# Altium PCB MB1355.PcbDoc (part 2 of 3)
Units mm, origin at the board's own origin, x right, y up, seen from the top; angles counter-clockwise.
Board outline 70.13 x 64.58 mm, 4 copper layers (L1, L2, L3, L4), stack 1.565 mm thick; 213 components, 161 nets, 1280 pads, 261 vias.
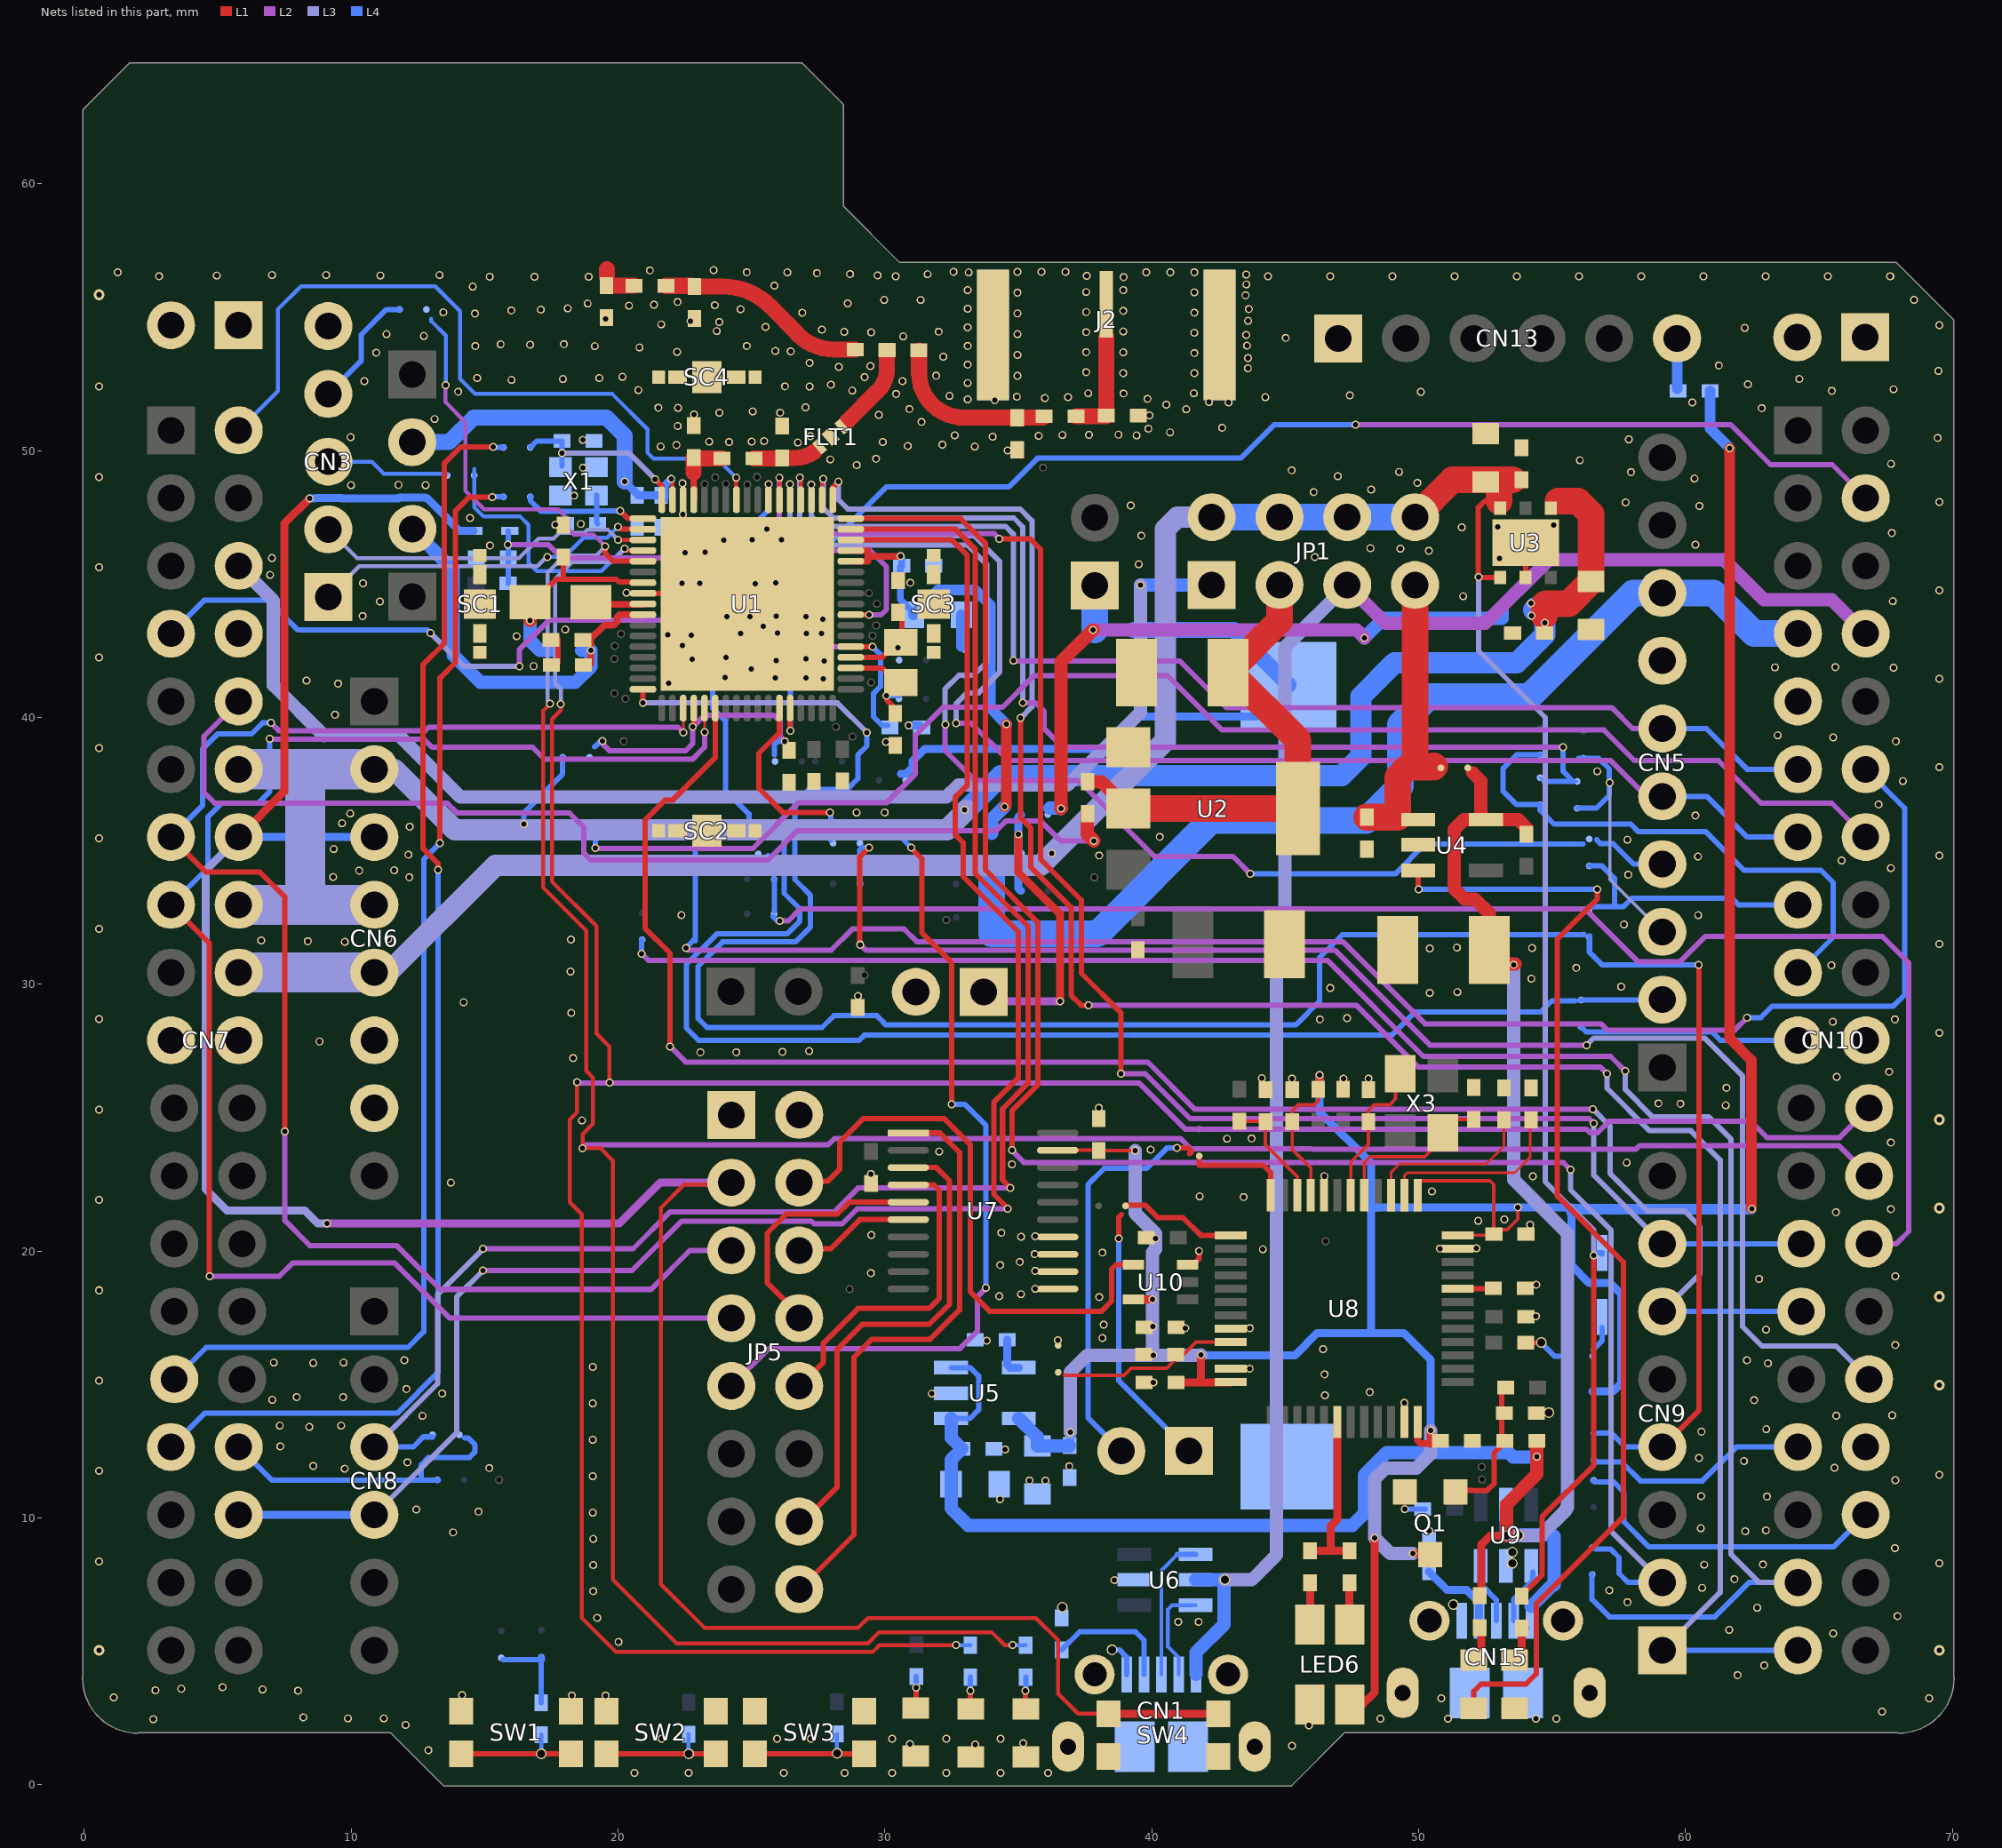
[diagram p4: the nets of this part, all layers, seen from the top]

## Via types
v1: diameter 0.3, hole 0.2, L1 to L4, tented both sides, 254 vias
v2: diameter 0.406, hole 0.203, L1 to L4, tented both sides, 7 vias

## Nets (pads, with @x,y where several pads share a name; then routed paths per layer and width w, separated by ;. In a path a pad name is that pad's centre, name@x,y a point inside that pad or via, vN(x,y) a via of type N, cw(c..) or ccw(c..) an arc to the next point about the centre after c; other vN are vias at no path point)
3V3: C13.1 C16.1 CN6.2 CN6.4 CN7.12 CN7.16 pad.105 pad.106 SB26.2 SB33.2 U3.4 | length 75.4
  L1 w1: 54.718,43.816 54.718,44.222 54.755,44.259 55.619,44.259 C13.1@56.46,45.1 56.46,47.616 55.967,48.109 55.224,48.109
  L3 w0.8: CN6.2@10.87,38.06 11.615,38.06 13.894,35.781 27.12,35.781 27.122,35.783 27.66,35.783 27.662,35.781 32.321,35.781 v1@33.055,36.515
  L3 w1.5: CN7.16@5.79,32.98 8.287,32.98 ; CN7.12@5.79,38.06 8.242,38.06 ; CN6.4@10.87,32.98 8.287,32.98 ; CN6.2@10.87,38.06 8.242,38.06 ; 8.242,38.06 8.287,38.015 8.287,32.98
  L4 w0.2: v1(16.475,36.002) 16.475,36.427 17.927,37.879 SB33.2@17.927,38.505
  L4 w0.8: v1@33.066,36.536 34.35,37.82 47.117,37.82 47.836,38.539 47.836,40.786 49.094,42.044 53.682,42.044 54.732,43.094 v1(54.732,43.547) 54.732,44.094 54.718,44.108 54.385,44.108 54.313,44.036
  other v1: 32.988,36.536
3V3_STLINK: C22.1 C27.1 C41.1 C43.1 C47.1 C48.1 C49.1 C50.1 LED6.4 pad.19 pad.37 pad.45 pad.47 pad.48 pad.59 Q1.3 R24.2 R30.1 R31.2 R32.2 SB37.1 U5.5 U7.19 U8.1 U8.9 U8.24 U8.36 U8.48 U10.5 | length 136.4
  L1 w0.127: U7.19@36.475,23.781 C41.1@37.996,23.781 ; C41.1@38.011,23.766 v1@39.375,23.766 ; 41.788,15.096 U8.24@42.96,15.096 ; U8.9@45.96,22.096 45.96,23.116 45.26,23.816 C47.1@45.26,24.857 45.26,25.256 45.49,25.486 46.09,25.486 46.24,25.636 R24.2@46.24,26.065 ; U8.1@49.96,22.096 49.96,22.636 52.67,22.636 52.81,22.496 52.81,20.647 C50.1@52.821,20.636 ; U8.48@51.46,20.596 52.781,20.596 C50.1@52.821,20.636 ; pad.59@53.716,21.644 53.716,21.197 53.32,20.801 52.986,20.801 C50.1@52.821,20.636
  L1 w0.25: U8.36@49.96,13.596 49.96,12.905 50.079,12.786 50.454,12.786
  L1 w0.3: U10.5@39.319,18.186 40.022,18.186 v1(40.028,18.192) ; C48.1@40.909,15.076 41.768,15.076 ; pad.37@41.842,16.111 41.842,15.15 41.788,15.096 41.768,15.076 ; U8.24@42.96,15.096 42.94,15.076 41.768,15.076 ; R24.2@46.24,26.065 46.279,26.104 v1(46.279,26.603) ; LED6.4@47.42,3.014 47.896,3.014 48.354,3.472 v1(48.354,9.252) ; v1(49.789,8.67) 50.391,8.67 Q1.3@50.432,8.629 ; pad.19@50.442,13.267 50.452,12.877 50.454,12.786 pad.19@50.454,13.279 pad.19@50.442,13.267
  L1 w0.4: v1(61.658,50.087) 61.658,27.969 62.465,27.162 v1@62.465,21.604
  L3 w0.3: v1@40.04,18.164 40.04,16.116 pad.48@40.056,16.1 ; pad.45@40.142,20.463 pad.45@40.142,20.469 ; pad.19@50.45,13.275 pad.19@50.45,13.294
  L3 w0.5: v1(36.942,13.207) 36.942,15.466 37.576,16.1 pad.48@40.056,16.1 41.831,16.1 pad.37@41.842,16.111 ; v1(39.375,23.764) 39.375,21.423 40.142,20.656 pad.45@40.142,20.469 ; pad.48@40.04,16.116 40.028,16.128 v1(40.028,18.192) 40.028,19.955 40.142,20.069 40.142,20.463 pad.45@40.139,20.466 ; v1(49.789,8.67) 48.936,8.67 v1(48.354,9.252) 48.354,11.455 48.773,11.874 49.92,11.874 50.45,12.404 50.45,13.275 pad.19@50.454,13.279
  L4 w0.3: C27.1@36.913,12.706 C27.1@36.92,12.713 36.942,12.735 v1(36.942,13.207) ; pad.37@41.83,16.094 45.36,16.094 46.2,16.934 48.22,16.934 ; v1(46.279,26.603) 46.281,26.601 46.281,25.233 48.22,23.294 48.22,21.624 ; pad.19@50.45,13.294 50.45,15.921 49.437,16.934 48.22,16.934 ; SB37.1@56.511,14.739 57.275,14.739 57.598,15.062 57.598,18.383 57.176,18.805 56.39,18.805 55.73,19.465 55.73,21.463 55.73,21.644 48.24,21.644 48.22,21.624 ; 48.22,16.934 48.22,21.624
  L4 w0.4: 55.73,21.463 55.837,21.57 v1@62.465,21.57 ; R31.2@60.925,52.233 60.925,50.82 v1(61.658,50.087)
  L4 w0.5: U5.5@35.02,13.731 35.71,13.041 C22.1@35.71,12.706 C27.1@36.913,12.706
  other v1: 62.477,21.592
5V: C14.1 C15.1 CN6.5 CN7.18 D2.1 JP1.2 JP1.4 JP1.6 JP1.8 pad.118 R10.1 SB28.2 U3.1 U3.6 | length 106.7
  L1 w0.2: v1@52.237,45.257 52.237,47.87 52.476,48.109 53.01,48.109 ; v1@52.286,45.249 U3.1@53.056,45.249 ; R10.1@53.97,7.073 53.97,7.212 54.623,7.865 54.623,10.039 56.561,11.977 v1(56.561,19.833)
  L1 w1: JP1.8@49.865,47.505 51.266,48.906 53.01,48.906 ; 53.01,48.109 53.01,48.906 ; 53.526,48.906 53.01,48.906
  L3 w0.2: v1(52.246,45.257) 52.246,42.498 54.744,40 54.744,22.6 56.561,20.783 v1(56.561,19.833)
  L3 w0.8: CN6.5@10.87,30.44 11.394,30.44 15.403,34.449 35.833,34.449 40.508,39.124 40.508,47.056 40.957,47.505 JP1.2@42.245,47.505
  L3 w1: 8.51,30.3 8.65,30.44
  L3 w1.5: CN7.18@5.79,30.44 8.65,30.44 CN6.5@10.87,30.44
  L4 w0.2: v1(56.561,19.833) 56.662,19.934 D2.1@56.87,19.934 56.87,19.894 D2.1@56.86,19.884
  L4 w1: JP1.2@42.245,47.505 JP1.4@44.785,47.505 JP1.6@47.325,47.505 JP1.8@49.865,47.505
5V_EXT: CN7.6 JP1.1 | length 48.3
  L3 w0.4: 8.98,39.314 11.799,39.314
  L3 w0.5: CN7.6@6.014,45.68 CN7.6@5.79,45.68 7.09,44.38 7.09,42.602 7.089,42.601 7.089,41.205 8.98,39.314 ; 11.799,39.314 14.093,37.02 32.306,37.02 32.748,37.462 36.844,37.462 39.575,40.193 v1(39.575,44.961) ; JP1.1@42.245,44.905 JP1.1@42.245,44.965
  L4 w0.5: v1(39.575,44.961) 42.241,44.961 JP1.1@42.245,44.965
5V_INT: C9.1 JP1.3 R33.2 U2.2 | length 18.6
  L1 w0.5: R33.2@37.593,37.594 38.115,37.594 U2.2@39.125,36.584
  L1 w1: U2.2@39.125,36.584 U2.2@45.475,36.584 45.475,39.153 C9.1@42.901,41.728 ; C9.1@42.857,41.684 C9.1@42.901,41.728 ; JP1.3@44.785,44.965 44.785,43.612 C9.1@42.901,41.728
5V_USB_MCU: CN1.1 CN10.8 JP1.5 pad.6 U6.5 | length 67
  L2 w0.5: JP1.5@47.325,44.965 48.76,43.53 52.49,43.53 54.874,45.914 61.432,45.914 62.932,44.414 65.476,44.414 CN10.8@66.75,43.14
  L3 w0.5: pad.6@42.738,7.684 43.747,7.684 44.68,8.617 44.68,30.984 44.99,31.294 44.99,42.63 JP1.5@47.325,44.965 ; CN10.8@66.75,43.074 CN10.8@66.75,43.14
  L4 w0.5: U6.5@41.641,7.684 42.705,7.684 42.705,6.009 41.659,4.963 CN1.1@41.659,4.135
5V_USB_STLINK: C11.1 C21.1 C25.1 CN15.1 pad.12 pad.13 pad.18 pad.64 pad.65 R11.1 R12.1 R16.2 SB25.2 U4.5 U5.1 U5.3 U9.5 | length 79.7
  L1 w0.3: R12.1@52.34,7.234 52.34,9.001 52.683,9.344 pad.12@53.3,9.344
  L1 w0.5: 52.035,37.914 52.335,37.614 52.335,36.358 U4.5@52.523,36.17 ; pad.12@53.3,9.344 53.3,10.513 54.433,11.646 R16.2@54.433,12.886 ; pad.65@53.604,30.754 53.175,30.754 C11.1@52.645,31.284 52.645,32.657 52.105,33.197 51.72,33.197 51.335,33.582 51.335,35.806 51.699,36.17 U4.5@52.523,36.17 ; R11.1@54.034,35.62 54.034,35.867 53.731,36.17 U4.5@52.523,36.17
  L3 w0.5: pad.12@53.3,9.344 54.57,9.344 55.53,10.304 55.53,10.362 55.57,10.402 55.57,20.666 53.56,22.676 pad.65@53.56,30.734
  L4 w0.2: U5.1@32.48,13.731 33.188,13.731 33.511,14.055 33.511,15.323 33.198,15.636 U5.3@32.48,15.636
  L4 w0.5: U5.1@32.48,13.731 32.48,13.005 C25.1@32.891,12.594 32.478,12.181 C21.1@32.478,11.274 32.478,10.364 33.118,9.724 39.252,9.724 ; 39.259,9.724 47.52,9.724 47.97,10.174 47.97,11.614 48.804,12.448 53.369,12.448 53.529,12.288 54.421,12.288 pad.18@54.429,12.296 ; pad.12@53.28,9.344 U9.5@53.28,10.234 ; pad.12@53.3,9.344 53.748,9.344 pad.13@53.751,9.347 ; pad.13@53.742,9.367 55.017,9.367 55.07,9.314 55.07,7.488 55.012,7.488 CN15.1@54.207,6.683
AIN_1: R26.1 R28.1 U8.10 | length 4.2
  L1 w0.127: R26.1@43.28,24.867 R28.1@44.25,24.867 ; R28.1@44.26,24.857 44.26,23.986 45.46,22.786 U8.10@45.46,22.096
ANT: C37.2 L3.2 | length 1.4
  L1 w0.6: 19.579,56.514 19.579,56.793 ; C37.2@19.646,56.307 19.646,56.177 L3.2@20.598,56.177
AT2: CN3.3 SB22.2 | length 4.6
  L4 w0.15: CN3.3@9.146,49.587 10.769,49.587 11.219,49.137 SB22.2@13.575,49.137
AT3: CN3.4 SB23.2 | length 4.6
  L4 w0.1: CN3.4@9.6,52.157 CN3.4@9.613,52.144
  L4 w0.2: CN3.4@9.146,52.127 10.372,53.353 10.372,54.334 11.325,55.287 SB23.2@11.813,55.287
AVDD: CN5.8 CN10.7 SB49.2 SB50.2 SB51.2 | length 40
  L3 w1: CN5.8@59.13,44.664 CN5.8@59.13,44.789
  L4 w1: 33.995,34.271 33.995,31.891 37.966,31.891 42.22,36.145 48.033,36.145 49.323,37.435 49.323,39.739 50.37,40.786 54.161,40.786 58.039,44.664 CN5.8@59.13,44.664 61.05,44.664 62.574,43.14 CN10.7@64.21,43.14
BOOT0: CN7.7 pad.99 R6.1 U1.5 | length 33.7
  L1 w0.2: U1.5@28.722,42.652 pad.99@29.533,42.652
  L2 w0.2: v1(16.303,41.911) 16.303,42.537 17.409,43.643 23.44,43.643 24.431,42.652 pad.99@29.533,42.652
  L3 w0.2: v1(12.979,43.159) 14.227,41.911 v1(16.303,41.911)
  L4 w0.2: CN7.7@3.25,43.14 4.499,44.389 6.894,44.389 8.01,43.273 12.865,43.273 v1(12.979,43.159) ; pad.99@29.533,42.652 29.833,42.352 29.833,41.164 29.565,40.896 29.565,40.035 29.905,39.695 R6.1@30.107,39.695
GND: C1.1 C2.1 C3.1 C4.2 C5.2 C6.2 C7.2 C8.2 C9.2 C10.2 C11.2 C12.2 C13.2 C14.2 C15.2 C16.2 C17.2 C18.2 C19.2 C20.2 C21.2 C22.2 C23.2 C24.2 C25.2 C26.2 C27.2 C28.2 C29.2 C31.2 C32.2 C33.1 C34.1 C36.2 C37.1 C39.1 C40.1 C41.2 C42.1 C43.2 C44.1 C45.1 C46.1 C47.2 C48.2 C49.2 C50.2 CN1.5 CN1.6 CN3.5 CN4.2 CN5.7 CN6.6 CN6.7 CN7.8 CN7.19 CN7.20 CN10.9 CN10.20 CN10.32 CN11.1 CN11.2 CN12.1 CN12.2 CN13.1 CN15.5 CN15.6 FLT1.2 J2.2 JP5.1 JP5.2 LED1.K LED2.K LED3.K LED5.K LED6.1 pad.7 pad.8 pad.9 pad.10 pad.11 pad.15 pad.21 pad.23 pad.24 pad.25 pad.26 pad.28 pad.29 pad.30 pad.31 pad.32 pad.33 pad.34 pad.35 pad.36 pad.38 pad.39 pad.40 pad.41 pad.42 pad.43 pad.46 pad.49 pad.50 pad.51 pad.52 pad.53 pad.54 pad.56 pad.57 pad.58 pad.60 pad.61 pad.62 pad.63 pad.66 pad.85 pad.92 pad.93 pad.111 pad.112 pad.113 pad.114 pad.115 pad.119 pad.120 pad.121 pad.125 pad.126 pad.139 pad.140 pad.141 pad.142 pad.143 pad.144 pad.145 pad.146 pad.147 pad.148 pad.149 pad.150 pad.151 pad.152 pad.153 pad.154 pad.155 pad.156 pad.157 pad.158 pad.159 pad.160 pad.161 pad.162 pad.163 pad.164 pad.165 pad.166 pad.168 pad.169 pad.170 pad.171 pad.172 pad.173 pad.174 pad.175 pad.176 pad.177 pad.178 pad.179 pad.180 pad.181 pad.182 pad.183 pad.184 pad.185 pad.186 pad.187 pad.188 pad.189 pad.190 pad.191 pad.192 pad.193 pad.194 pad.195 pad.196 pad.197 pad.198 pad.199 pad.200 pad.201 pad.202 pad.203 pad.204 pad.205 pad.206 pad.207 pad.208 pad.209 pad.210 pad.211 pad.212 pad.213 pad.214 pad.215 pad.216 pad.217 pad.218 pad.219 pad.220 pad.221 pad.222 pad.223 pad.224 pad.225 pad.226 pad.227 pad.228 pad.229 pad.230 pad.231 pad.232 pad.233 pad.234 pad.235 pad.236 pad.237 pad.238 pad.239 pad.241 pad.242 pad.243 pad.244 pad.245 pad.246 pad.247 pad.248 pad.249 pad.250 pad.251 pad.254 pad.255 pad.256 pad.257 pad.258 pad.259 pad.260 pad.261 pad.262 pad.263 pad.264 pad.265 pad.266 pad.267 pad.268 pad.269 pad.270 pad.271 pad.272 pad.273 pad.274 pad.275 pad.276 pad.277 pad.278 pad.279 pad.280 pad.281 pad.282 pad.283 pad.284 pad.285 pad.286 pad.287 pad.288 pad.289 pad.290 pad.291 pad.292 pad.293 pad.294 pad.295 pad.296 pad.297 pad.298 pad.299 pad.300 pad.301 pad.302 pad.303 pad.304 pad.305 pad.306 pad.307 pad.308 pad.309 pad.310 pad.311 pad.312 pad.313 pad.314 pad.315 pad.316 pad.318 pad.319 pad.320 pad.321 pad.322 pad.323 pad.325 pad.326 pad.327 pad.328 pad.329 pad.330 pad.332 pad.333 pad.334 pad.335 pad.336 pad.337 pad.338 pad.339 pad.340 pad.342 pad.343 pad.344 pad.345 pad.346 pad.347 pad.348 pad.349 pad.350 pad.351 pad.352 pad.353 pad.354 pad.355 pad.356 pad.357 pad.358 pad.359 pad.360 pad.361 pad.362 pad.363 pad.364 pad.365 pad.366 pad.367 pad.368 pad.369 pad.370 pad.371 pad.372 pad.373 pad.374 pad.375 pad.376 pad.377 pad.378 pad.379 pad.380 pad.381 pad.382 pad.383 pad.384 pad.385 pad.386 pad.387 pad.388 pad.389 pad.390 pad.391 pad.392 pad.393 pad.394 pad.395 pad.396 pad.397 pad.398 pad.399 pad.400 pad.401 pad.402 pad.403 pad.404 pad.405 pad.406 pad.407 pad.408 pad.409 pad.410 pad.411 pad.412 pad.413 pad.414 pad.415 pad.416 pad.417 pad.418 pad.419 pad.420 pad.421 pad.422 pad.423 pad.424 pad.425 pad.426 pad.427 pad.429 pad.430 pad.431 pad.432 pad.433 pad.434 pad.435 pad.436 pad.437 pad.438 pad.439 pad.440 pad.441 pad.442 pad.443 pad.444 pad.445 pad.446 pad.447 pad.448 pad.449 pad.450 pad.451 pad.452 pad.453 pad.454 pad.455 pad.456 pad.457 pad.458 pad.459 pad.460 pad.461 pad.462 pad.463 pad.464 pad.465 pad.466 pad.467 pad.468 pad.469 pad.470 pad.471 pad.472 pad.473 pad.474 pad.475 pad.476 pad.477 pad.478 pad.479 pad.480 pad.481 pad.482 pad.483 pad.484 pad.485 pad.486 pad.487 pad.488 pad.489 pad.490 pad.491 pad.492 pad.493 pad.494 pad.495 pad.496 pad.497 pad.498 pad.499 pad.500 pad.501 pad.502 pad.503 pad.504 pad.505 pad.506 pad.507 pad.508 pad.509 pad.510 pad.511 pad.512 pad.513 pad.514 pad.515 pad.516 pad.517 pad.518 pad.519 pad.520 pad.521 pad.522 pad.523 pad.524 pad.525 pad.526 pad.527 pad.528 pad.529 pad.530 pad.531 pad.532 pad.533 pad.534 pad.535 pad.536 pad.537 pad.538 pad.539 pad.540 pad.541 pad.542 pad.543 pad.544 pad.545 pad.546 pad.547 pad.548 pad.549 pad.550 pad.551 pad.552 pad.553 pad.554 pad.555 pad.556 pad.557 pad.558 pad.559 pad.560 pad.561 pad.562 pad.563 pad.564 pad.565 pad.566 pad.567 pad.568 pad.569 pad.570 pad.571 pad.572 pad.573 pad.574 pad.575 pad.576 pad.577 pad.578 pad.580 pad.581 R1.1 R6.2 R15.2 R18.2 R19.1 R20.1 R22.2 R23.1 R28.2 SB40.2 SC1.1 SC2.1 SC3.1 SC4.1 SK_BT1.2 SW1.1 SW2.1 SW3.1 SW4.2 U1.32 U1.42 U1.69 U2.1 U3.2 U3.7 U4.2 U5.2 U6.2 U7.11 U7.12 U7.13 U7.14 U8.8 U8.20 U8.23 U8.35 U8.47 U9.2 U10.3 X1.2 X1.4 | length 13.7
  L1 w0.2: C23.2@17.756,42.035 C24.2@17.756,42.951 ; U1.42@20.941,44.652 U1.69@24.444,44.652 ; U1.32@22.444,48.155 22.444,46.652 U1.69@24.444,44.652 ; U1.69@24.844,44.252 U1.69@24.444,44.652 ; U10.3@41.346,19.486 41.543,19.486 41.768,19.711 pad.46@41.768,20.006 ; U3.2@54.006,45.249 U3.7@54.006,46.549 ; R20.1@54.415,13.933 54.432,13.95 pad.15@54.877,13.95
  L4 w0.1: R6.2@31.304,39.705 R6.2@31.38,39.629
  L4 w0.203: pad.8@38.51,5.064 38.78,5.064 39.059,4.785 CN1.5@39.059,4.135
  L4 w0.3: pad.120@30.889,39.705 R6.2@31.304,39.705
  other v1: 20.62,0.452 22.652,0.452 26.208,0.452 28.494,0.452 30.272,0.452 32.304,0.452 34.336,0.452 36.114,0.452 45.258,1.468 33.39,1.504 30.93,1.524 35.18,1.564 21.636,1.722 25.954,1.722 27.224,1.722 30.272,1.722 32.304,1.722 34.336,1.722 45.89,2.224 48.56,2.484 51.1,2.484 54.402,2.484 55.164,2.484 67.356,2.738 50.846,3.246 69.134,3.246 1.11,3.284 69.51,8.301 0.554,8.373 69.51,11.616 0.554,11.76 65.578,11.882 0.554,15.147 0.554,18.533 0.554,21.92 0.554,25.307 69.51,28.188 0.554,28.693 69.51,31.503 0.554,32.08 69.51,34.817 0.554,35.467 69.51,38.132 0.554,38.853 69.51,41.446 0.554,42.24 69.51,44.761 0.554,45.627 69.51,48.075 0.554,49.013 46.973,49.04 0.554,52.4 69.51,54.704 68.56,55.644 44.362,56.534 46.693,56.534 49.023,56.534 51.354,56.534 53.685,56.534 56.016,56.534 58.347,56.534 60.678,56.534 63.008,56.534 65.339,56.534 67.67,56.534 1.25,56.684
  other v2: 0.554,5.04 69.51,5.04 69.51,14.983 69.51,18.298 69.51,21.612 69.51,24.927 0.554,55.84
LED_STLK: R25.2 R27.2 U8.30 | length 6.4
  L1 w0.3: R25.2@45.93,8.773 46.71,8.773 ; U8.30@46.96,13.596 46.96,9.952 46.71,9.702 46.71,8.773 ; R27.2@47.41,8.773 46.71,8.773
NetC1_2: C1.2 L5.1 U1.31 | length 2.4
  L1 w0.26: 22.838,49.173 U1.31@22.844,48.155
  L1 w0.32: C1.2@22.836,49.736 C1.2@22.844,49.728
  L1 w0.6: C1.2@22.836,49.736 22.838,49.173 ; 23.117,49.703 L5.1@23.896,49.703
NetC2_2: C2.2 FLT1.1 L5.2 | length 1.9
  L1 w0.6: L5.2@25.094,49.703 C2.2@26.038,49.703 ; 26.417,49.727 ccw(c26.579,51.089) 27.359,49.961
NetC3_2: C3.2 D1.A pad.102 R5.2 U1.8 | length 20
  L1 w0.2: U1.8@28.722,43.852 28.729,43.845 pad.102@29.411,43.845
  L2 w0.2: v1(15.88,46.479) 17.382,46.479 17.886,45.975 20.106,45.975 20.112,45.969 20.402,45.969 20.408,45.975 21.826,45.975 22.397,46.546 23.414,46.546 23.699,46.261 29.446,46.261 30.062,45.645 30.062,44.044 29.863,43.845 pad.102@29.411,43.845
  L4 w0.2: R5.2@15.881,45.028 D1.A@15.881,46.998
NetC4_1: C4.1 pad.69 SB44.1 U1.34 X1.3 | length 7
  L1 w0.2: pad.69@21.391,48.926 21.644,48.673 U1.34@21.644,48.155
  L3 w0.2: v1(17.905,49.911) 20.406,49.911 pad.69@21.391,48.926
  L4 w0.2: SB44.1@16.714,50.119 16.956,50.361 C4.1@17.9,50.361 v1@17.9,49.911 ; X1.3@17.9,49.422 v1@17.9,49.911 ; v1(17.905,49.911) v1@17.9,49.911
NetC5_1: C5.1 SB43.1 U1.35 X1.1 | length 5.7
  L1 w0.2: v1(20.09,47.739) 20.377,47.452 U1.35@20.941,47.452
  L4 w0.2: SB43.1@16.714,48.268 16.714,48.125 17.11,47.729 19.2,47.729 19.201,47.73 ; X1.1@19.201,48.323 19.201,47.73 ; C5.1@19.236,47.259 19.201,47.294 19.201,47.73 ; v1(20.09,47.739) 19.21,47.739 19.201,47.73
NetC6_1: C6.1 pad.110 SB45.1 U1.3 X2.1 | length 3.1
  L1 w0.2: U1.3@28.722,41.852 29.899,41.852 X2.1@30.444,41.307 ; pad.110@30.058,40.815 30.07,40.803 30.07,40.654 C6.1@30.393,40.331
  L4 w0.2: pad.110@30.058,40.815 30.529,40.815 30.545,40.831
NetC7_1: C7.1 pad.134 SB46.1 U1.4 X2.2 | length 3
  L1 w0.2: U1.4@28.722,42.252 29.899,42.252 30.454,42.807 X2.2@30.591,42.807 30.643,42.859 C7.1@30.643,43.695
NetC12_1: C12.1 JP1.7 SB25.1 U4.1 | length 11.8
  L1 w1: C12.1@48.057,36.263 49.215,36.263 49.215,37.76 49.595,38.14 50.569,38.14 ; JP1.7@49.865,44.965 49.865,38.14 50.569,38.14 ; 50.569,38.192 50.595,38.166 50.569,38.14
NetC23_1: C23.1 C24.1 JP6.2 pad.107 SB31.2 U1.44 | length 15.7
  L1 w0.25: C24.1@18.964,42.935 19.487,43.458 19.843,43.458 19.975,43.59 19.975,43.773 20.054,43.852 U1.44@20.941,43.852 ; C23.1@18.982,42.003 C24.1@18.982,42.917
  L4 w0.25: JP6.2@12.296,47.063 JP6.2@12.524,47.063 ; pad.107@18.975,42.506 pad.107@18.983,42.514
  L4 w0.5: JP6.2@12.296,47.063 13.829,45.53 13.829,42.337 14.844,41.322 18.409,41.322 18.983,41.896 pad.107@18.983,42.514 ; 18.637,42.506 pad.107@18.975,42.506
NetC26_1: C26.1 U5.4 | length 1.4
  L4 w0.3: C26.1@34.589,16.674 34.589,15.743 34.695,15.636 U5.4@35.02,15.636
NetC29_1: C29.1 L1.1 pad.108 SB31.1 U1.41 | length 7.9
  L1 w0.2: L1.1@16.702,44.318 16.827,44.318 17.693,45.184 17.951,45.184 ; C29.1@17.951,46.01 17.951,45.184 ; U1.41@20.941,45.052 20.941,45.07 20.049,45.07 19.935,45.184 17.951,45.184
  L1 w0.5: pad.108@16.702,43.63 L1.1@16.702,44.318
  L4 w0.5: pad.108@16.702,43.63 16.702,42.878 17.074,42.506 SB31.1@17.502,42.506
NetC31_1: C31.1 pad.136 SB33.1 SB34.1 U1.55 | length 10.6
  L1 w0.2: v1(22.805,39.645) 22.778,39.645 22.844,39.711 U1.55@22.844,40.349
  L2 w0.2: v1(19.411,39.111) 19.411,39.029 19.692,38.748 22.531,38.748 22.805,39.022 v1(22.805,39.645) 23.245,40.085 25.831,40.085 26.083,39.833 26.083,39.274 pad.136@26.249,39.108
  L4 w0.2: 19.122,38.894 19.339,39.111 v1(19.411,39.111) ; 25.863,38.605 25.863,38.991 25.98,39.108 pad.136@26.249,39.108
NetC32_1: C32.1 L2.2 pad.122 SB49.1 U1.13 U1.14 | length 17.8
  L1 w0.25: U1.13@28.722,45.852 29.365,45.852 29.365,46.252 U1.14@28.722,46.252 ; 29.491,46.042 30.588,46.042 pad.122@30.592,46.046
  L1 w0.4: v1(34.485,36.659) 34.551,36.725 v1(34.551,39.746)
  L4 w0.25: pad.122@30.592,46.046 30.631,46.007 C32.1@30.631,45.689 30.576,45.634 30.576,44.416 31.063,43.929 L2.2@31.063,43.852
  L4 w0.4: L2.2@31.063,43.852 31.985,44.774 33.387,44.774 33.943,44.218 33.943,40.354 v1(34.551,39.746) v1@34.559,39.738
  L4 w0.5: SB49.1@33.994,35.649 33.994,36.168 v1(34.485,36.659)
NetC33_2: C33.2 C34.2 JP4.2 pad.67 U1.33 | length 13.6
  L1 w0.1: pad.67@21.991,48.937 pad.67@22.044,48.884
  L1 w0.15: U1.33@22.044,48.155 pad.67@22.044,48.884
  L4 w0.3: v1(20.257,48.832) 20.753,48.336 20.753,48.327 C34.2@21.68,48.327 ; C34.2@21.752,48.215 21.752,48.698 pad.67@21.991,48.937
  L4 w0.6: JP4.2@12.289,50.316 13.672,50.316 14.598,51.242 19.574,51.242 20.257,50.559 v1(20.257,48.832)
NetC35_1: C35.1 C38.1 FLT1.3 | length 3
  L1 w0.6: 28.586,51.096 29.712,52.221 ; 29.721,52.221 ccw(c28.911,53.062) 30.077,53 C38.1@30.077,53.517
NetC35_2: C35.2 C36.1 L3.1 | length 7.9
  L1 w0.32: C36.1@22.798,56.173 C36.1@22.82,56.151 ; 26.728,54.383 26.728,54.387
  L1 w0.6: L3.1@21.8,56.173 C36.1@22.798,56.173 ; C36.1@22.82,56.151 23.912,56.151 cw(c23.912,53.611) 25.708,55.407 26.728,54.383 ; 26.728,54.358 ccw(c28.097,55.726) 28.097,53.791 C35.2@28.881,53.791
NetC38_2: C38.2 C39.2 L4.1 | length 6.5
  L1 w0.32: L4.1@35.919,51.237 L4.1@35.971,51.289
  L1 w0.6: C38.2@31.279,53.758 31.279,52.885 ccw(c32.952,52.909) 32.999,51.237 L4.1@35.919,51.237
NetC40_2: C40.2 J2.1 L4.2 | length 5.3
  L1 w0.32: C40.2@38.275,51.289 C40.2@38.296,51.31 ; J2.1@38.298,54.253 J2.1@38.298,55.481
  L1 w0.6: L4.2@37.169,51.289 C40.2@38.275,51.289 ; C40.2@38.296,51.31 38.296,54.251 J2.1@38.298,54.253
NetC44_2: C44.2 U8.6 X3.1 | length 5.6
  L1 w0.127: U8.6@47.46,22.096 47.46,23.346 48.12,24.006 C44.2@48.12,24.857 48.12,25.269 48.337,25.486 48.915,25.486 49.138,25.709 X3.1@49.138,26.65
NetC45_2: C45.2 U8.5 X3.3 | length 6
  L1 w0.127: U8.5@47.96,22.096 47.96,23.316 48.178,23.534 50.224,23.534 50.738,24.048 X3.3@50.738,24.45 ; X3.3@50.942,24.44 51.435,24.933 C45.2@52.064,24.933
NetCN1_2: CN1.2 U6.6 | length 3.7
  L4 w0.14: CN1.2@41.009,4.135 41.009,4.772 40.604,5.177 40.604,6.568 40.77,6.734 U6.6@41.641,6.734
NetCN1_3: CN1.3 U6.4 | length 5.4
  L4 w0.14: CN1.3@40.359,4.135 40.359,8.027 40.966,8.634
  L4 w0.2: 40.966,8.634 U6.4@41.641,8.634
NetCN1_4: CN1.4 R1.2 | length 4.8
  L4 w0.2: R1.2@36.627,5.061 37.299,5.733 39.394,5.733 39.709,5.418 CN1.4@39.709,4.135
NetCN3_1: CN3.1 pad.96 U1.36 | length 12.8
  L1 w0.2: pad.96@20.104,47.052 U1.36@20.941,47.052
  L3 w0.15: CN3.1@9.146,44.507 10.308,45.669 16.979,45.669 17.35,46.04 17.373,46.017 v1(17.349,46.017)
  L4 w0.15: v1(17.349,46.017) 17.996,46.017 18.712,46.733 19.588,46.733 pad.96@19.997,47.142
NetCN3_2: CN3.2 pad.95 U1.37 | length 12.9
  L1 w0.15: pad.95@20.006,46.652 U1.37@20.941,46.652
  L3 w0.15: CN3.2@9.146,47.047 10.219,45.974 11.828,45.974 11.84,45.962 12.752,45.962 12.764,45.974 16.301,45.974 17.026,46.699 17.588,46.699 17.814,46.925 18.743,46.925 18.858,47.04 19.618,47.04 pad.95@20.006,46.652
NetCN4_1: CN4.1 pad.117 SB24.1 SB27.1 SB28.1 | length 12.8
  L1 w0.3: pad.117@35.008,35.615 35.008,34.184 36.558,32.634 v1(36.558,29.366)
  L2 w0.3: CN4.1@33.71,29.707 34.051,29.366 v1(36.558,29.366)
  L4 w0.3: SB24.1@35.097,33.5 34.997,33.6 34.997,36.261 SB27.1@35.097,36.361
NetCN5_3: CN5.3 SB41.2 SB42.2 | length 10.1
  L3 w0.127: v1(57.165,37.557) 57.165,33.929 CN5.3@59.13,31.964
  L4 w0.127: 56.648,36.596 56.65,36.594 56.66,36.604
  L4 w0.2: SB41.2@55.94,36.596 56.648,36.596 ; 56,38.466 56.748,38.466 57.14,38.074 57.14,37.084 56.66,36.604
NetCN7_10: CN7.10 pad.585 R33.1 | length 41
  L1 w0.5: R33.1@37.593,36.396 37.583,36.386 37.583,35.62 pad.585@37.828,35.375
  L2 w0.2: CN7.10@5.79,40.6 4.487,39.297 4.487,37.191 4.891,36.787 13.609,36.787 13.977,36.419 18.188,36.419 18.722,35.885 18.722,34.911 18.98,34.653 25.619,34.653 26.723,35.757 34.172,35.757 34.54,36.125 35.827,36.125 36.504,35.448 36.522,35.448 36.595,35.375 pad.585@37.828,35.375
NetCN7_32: CN7.32 SB14.1 SB16.1 | length 11.6
  L4 w0.2: CN7.32@5.79,12.66 7.038,11.412 12.625,11.412 ; SB16.1@13.278,11.412 12.625,11.412 ; 14.257,13.006 14.384,13.006 14.638,12.752 14.638,12.471 14.439,12.272 12.897,12.272 12.625,12 12.625,11.412
NetCN10_12: CN10.12 pad.132 pad.133 SB2.2 | length 61.6
  L2 w0.2: v1(22.541,31.362) 22.626,31.277 27.986,31.277 28.778,32.069 30.721,32.069 31.193,31.597 47.159,31.597 50.24,28.516 56.839,28.516 57.068,28.287 61.848,28.287 pad.132@62.308,28.747
  L4 w0.2: v1(22.541,31.362) 22.814,31.635 22.902,31.635 SB2.2@22.902,35.586 ; pad.132@62.308,28.747 62.814,28.747 63.249,29.182 67.782,29.182 68.21,29.61 68.21,36.6 CN10.12@66.75,38.06
NetCN10_14: CN10.14 SB4.2 | length 54.6
  L2 w0.2: v1(19.158,35.099) 19.161,35.097 25.062,35.097 26.771,36.806 30.068,36.806 31.141,37.879 31.141,39.333 32.183,40.375 34.402,40.375 35.595,41.568 35.595,41.573 40.591,41.573 42.635,39.529 56.941,39.529 58.084,38.386 61.231,38.386 62.829,36.788 65.482,36.788 CN10.14@66.75,35.52
  L3 w0.2: v1@19.156,35.099 v1(19.158,35.099)
  L4 w0.2: v1(19.158,35.099) 19.158,35.396 19.366,35.604 SB4.2@19.726,35.604
NetCN10_15: CN10.15 SB1.1 SB3.1 | length 10.2
  L4 w0.2: SB1.1@56.39,34.434 56.869,34.434 57.334,33.969 57.334,32.904 ; SB3.1@56.4,32.904 57.334,32.904 ; CN10.15@64.21,32.98 61.984,32.98 61.74,33.224 57.99,33.224 57.67,32.904 57.334,32.904
NetCN10_17: CN10.17 SB5.1 SB6.1 | length 20.3
  L4 w0.2: SB6.1@54.57,38.594 53.67,38.594 53.17,38.094 53.17,37.234 53.67,36.734 SB5.1@54.55,36.734 54.55,36.524 55.07,36.004 57.945,36.004 58.235,35.714 60.759,35.714 62.199,34.274 65.07,34.274 65.53,33.814 65.53,31.76 CN10.17@64.21,30.44
NetCN10_19: CN10.19 SB8.1 | length 8.3
  L4 w0.2: SB8.1@56.09,28.404 56.28,28.214 60.99,28.214 61.304,27.9 CN10.19@64.21,27.9
NetCN10_26: CN10.26 SB7.2 SB9.2 SB10.2 | length 57.9
  L2 w0.2: v1(26.065,32.377) 26.379,32.377 26.821,32.819 56.253,32.819 58.232,30.84 59.784,30.84 60.745,31.801 67.363,31.801 68.36,30.804 68.36,20.738 67.902,20.28 CN10.26@66.877,20.28
  L4 w0.2: 25.573,34.302 25.626,34.355 25.626,34.821 ; SB7.2@25.811,32.528 25.962,32.377 v1(26.065,32.377) ; SB9.2@25.848,33.937 25.855,33.93 SB7.2@25.855,32.739
NetCN10_30: CN10.30 SB12.2 SB13.2 | length 55.7
  L1 w0.2: v1(29.081,31.485) 29.061,31.485 29.061,34.781 v1(29.404,35.124)
  L2 w0.2: v1(29.081,31.485) 29.283,31.283 46.855,31.283 50.419,27.719 v1(56.291,27.719)
  L3 w0.2: v1(56.291,27.719) 56.557,27.985 57.947,27.985 57.948,27.984 60.717,27.984 62.127,26.574 62.127,17.178 62.861,16.444 65.633,16.444 CN10.30@66.877,15.2
  L4 w0.2: SB12.2@29.052,33.784 29.052,35.035 29.141,35.124 v1(29.404,35.124)
NetCN10_31: CN10.31 SB11.1 | length 8.5
  L4 w0.2: SB11.1@56.571,12.169 56.641,12.099 57.599,12.099 58.31,11.388 60.634,11.388 61.906,12.66 CN10.31@64.21,12.66
NetCN10_34: CN10.34 SB17.2 | length 12.4
  L4 w0.2: SB17.2@56.54,11.406 56.595,11.351 57.312,11.351 57.698,10.965 57.698,9.852 58.635,8.915 65.545,8.915 CN10.34@66.75,10.12
NetCN10_35: CN10.35 SB15.1 SB18.1 | length 72.6
  L2 w0.2: v1(20.883,31.147) 21.132,30.898 46.579,30.898 50.179,27.298 57.192,27.298 v1(57.744,26.746)
  L3 w0.2: v1(57.744,26.746) 57.744,26.056 58.77,25.03 60.874,25.03 61.698,24.206 61.698,8.642 62.76,7.58 CN10.35@64.21,7.58
  L4 w0.2: v1(20.883,31.147) 20.883,31.649 SB18.1@20.905,31.671 ; SB15.1@56.498,7.881 56.498,6.942 57.144,6.296 61.096,6.296 62.38,7.58 CN10.35@64.21,7.58
NetCN13_6: CN13.6 R31.1 | length 1.9
  L4 w0.4: R31.1@59.68,52.325 CN13.6@59.68,54.204
NetCN14_1: CN14.1 SB39.2 U8.13 | length 14.4
  L1 w0.2: v1(38.769,20.473) 38.769,21.28 38.868,21.379 ; SB39.2@39.04,21.716 39.763,21.716 40.23,21.249 41.175,21.249 41.828,20.596 U8.13@42.96,20.596
  L4 w0.2: v1(38.769,20.473) 38.769,15.138 CN14.1@41.398,12.509
NetCN14_2: CN14.2 SB38.2 U8.12 | length 19.1
  L1 w0.2: v1(40.943,23.861) 41.364,23.861 41.496,23.729 41.416,23.649 ; 41.77,23.221 44.155,23.221 44.18,23.196 44.19,23.206 44.46,22.936 U8.12@44.46,22.096 ; 41.78,23.231 SB38.2@41.78,23.568
  L4 w0.2: CN14.2@38.858,12.509 37.61,13.757 37.61,22.492 38.214,23.096 39.803,23.096 40.568,23.861 v1(40.943,23.861)
NetCN15_2: CN15.2 U9.1 | length 2.1
  L4 w0.2: CN15.2@53.557,6.15 53.557,6.941 54.27,7.654 U9.1@54.27,7.974
NetCN15_3: CN15.3 U9.3 | length 2
  L4 w0.2: U9.3@52.37,7.974 52.37,7.474 52.907,6.937 CN15.3@52.907,6.15
NetCN15_4: CN15.4 R23.2 | length 3
  L4 w0.3: R23.2@50.39,7.985 51.071,7.304 51.8,7.304 52.257,6.847 CN15.4@52.257,6.15
NetD2_2: D2.2 SB36.1 | length 1
  L4 w0.2: 56.566,16.277 56.566,16.34 56.88,16.654 D2.2@56.88,17.144
NetJP2_1: JP2.1 SB26.1 SB27.2 SB29.2 | length 25.3
  L1 w0.5: v1(36.602,36.59) 36.602,42.086 v1(37.793,43.277)
  L2 w0.5: v1(37.793,43.277) 47.679,43.277 v1(47.968,42.988)
  L4 w0.5: 36.186,36.604 36.602,36.604 v1(36.602,36.59) ; v1(47.968,42.988) 48.695,43.715 53.131,43.715 SB26.1@53.131,43.954
  L4 w1: v1@37.867,43.277 JP2.1@37.867,44.946
NetJP5_4: JP5.4 U10.4 | length 21.6
  L1 w0.2: JP5.4@26.859,22.627 27.861,22.627 28.316,23.082 28.316,24.093 29.183,24.96 32.232,24.96 33.198,23.994 33.198,18.478 33.925,17.751 38.116,17.751 38.492,18.127 38.492,19.314 38.664,19.486 U10.4@39.319,19.486
NetJP5_6: JP5.6 U7.6 | length 4.5
  L1 w0.2: JP5.6@26.859,20.087 27.971,20.087 29.065,21.181 U7.6@30.875,21.181
NetJP5_8: JP5.8 U7.5 | length 9.4
  L1 w0.2: JP5.8@26.859,17.547 25.589,18.817 25.589,20.672 26.306,21.389 28.223,21.389 28.665,21.831 U7.5@30.875,21.831
NetJP5_10: JP5.10 U7.4 | length 12.2
  L1 w0.2: JP5.10@26.859,15.007 27.695,15.843 27.695,16.555 28.996,17.856 31.665,17.856 32.031,18.222 32.031,22.287 31.837,22.481 U7.4@30.875,22.481
NetJP5_14: JP5.14 U7.3 | length 18.5
  L1 w0.2: JP5.14@26.783,9.726 28.2,11.143 28.2,16.303 29.16,17.263 31.672,17.263 32.423,18.014 32.423,22.638 31.93,23.131 U7.3@30.875,23.131
NetJP5_16: JP5.16 U7.1 | length 22.3
  L1 w0.2: JP5.16@26.859,7.387 28.841,9.369 28.841,16.025 29.516,16.7 31.698,16.7 32.795,17.797 32.795,23.704 32.068,24.431 U7.1@30.875,24.431
NetL1_2: L1.2 U1.43 | length 1.9
  L1 w0.25: L1.2@19.09,44.349 19.194,44.245 20.941,44.245 U1.43@20.941,44.252
NetL2_1: L2.1 SB35.1 | length 1.2
  L4 w0.4: 32.867,42.666 L2.1@32.867,43.852
NetLED1_A: LED1.A R2.2 | length 1.2
  L1 w0.2: LED1.A@31.15,2.876 ccw(c31.1,2.926) 31.171,2.926 v1(31.171,3.645)
  L4 w0.2: v1(31.171,3.645) 31.171,4.06 R2.2@31.175,4.065
NetLED2_A: LED2.A R3.2 | length 1.2
  L1 w0.2: v1(33.198,3.52) 33.198,2.899 ccw(c33.273,2.899) LED2.A@33.22,2.846
  L4 w0.2: v1(33.198,3.52) 33.205,3.527 R3.2@33.205,4.035
NetLED3_A: LED3.A R4.2 | length 1.2
  L1 w0.2: v1(35.274,3.52) 35.274,2.852 LED3.A@35.28,2.846
  L4 w0.2: v1(35.274,3.52) v1(35.274,3.52) R4.2@35.275,4.035
NetLED4_A: LED4.A R12.2 | length 1.3
  L1 w0.3: LED4.A@52.069,4.672 52.34,4.943 R12.2@52.34,5.895
NetLED4_K: LED4.K U4.3 | length 43
  L1 w0.2: U4.3@49.983,34.265 49.983,33.573 v1(49.995,33.561) ; LED4.K@52.069,2.868 52.069,3.509 52.335,3.775 54.022,3.775 54.407,4.16 54.407,6.777 57.669,10.039 57.669,19.591 55.201,22.059 55.201,31.697 56.689,33.185 v1(56.689,33.561)
  L4 w0.2: v1(49.995,33.561) v1(56.689,33.561)
NetLED5_A: LED5.A R10.2 | length 1.4
  L1 w0.3: LED5.A@53.593,4.672 53.863,4.942 53.863,5.768 R10.2@53.97,5.875
NetLED6_2: LED6.2 R25.1 | length 1.6
  L1 w0.3: LED6.2@45.93,6.024 R25.1@45.93,7.575
NetLED6_3: LED6.3 R27.1 | length 1.6
  L1 w0.3: LED6.3@47.41,6.024 R27.1@47.41,7.575
NetQ1_1: Q1.1 R16.1 R17.1 R20.2 | length 5.2
  L1 w0.2: Q1.1@51.2,11.036 52.577,11.036 52.821,11.28 52.821,12.436 53.114,12.729 R17.1@53.114,14.67
NetQ1_2: pad.22 Q1.2 R21.2 | length 1.5
  L1 w0.127: pad.22@49.477,10.329 49.491,10.343 Q1.2@49.491,11.079
  L4 w0.2: pad.22@49.46,10.334 R21.2@50.241,10.334
NetR7_1: pad.2 R7.1 SW1.2 | length 4.8
  L1 w0.2: SW1.2@14.103,1.167 SW1.2@14.13,1.167 SW1.2@18.203,1.167
  L4 w0.15: pad.2@17.124,1.163 R7.1@17.124,1.879
NetR7_2: R7.2 SB47.1 SB48.1 | length 3.2
  L4 w0.2: SB47.1@15.694,4.693 17.174,4.693 SB48.1@17.174,4.735 ; R7.2@17.124,3.077 SB48.1@17.124,4.785
NetR8_1: pad.3 R8.1 SW2.2 | length 4.8
  L1 w0.2: SW2.2@19.564,1.167 SW2.2@23.664,1.167
  L4 w0.15: R8.1@22.646,1.897 22.646,1.172 pad.3@22.655,1.163
NetR9_1: pad.4 pad.5 R9.1 SW3.2 | length 4.8
  L1 w0.2: SW3.2@25.127,1.167 SW3.2@29.227,1.167
  L4 w0.15: R9.1@28.203,1.905 28.203,1.19 pad.4@28.212,1.181
NetR14_1: pad.14 R14.1 SB36.2 | length 1.7
  L1 w0.2: R14.1@54.009,16.566 54.588,16.566 pad.14@54.598,16.576
  L4 w0.2: pad.14@54.585,16.567 55.085,16.067 SB36.2@55.515,16.067
NetR18_1: R18.1 U8.2 | length 7.1
  L1 w0.1: U8.2@49.46,22.096 49.46,22.826 49.573,22.939 53.595,22.939 54.182,23.526 R18.1@54.182,24.857
NetR19_2: R19.2 U8.44 | length 1.3
  L1 w0.2: U8.44@51.46,18.596 R19.2@52.791,18.596
NetR22_1: R22.1 U8.3 | length 6.5
  L1 w0.1: U8.3@48.96,22.096 48.96,22.946 49.28,23.266 52.531,23.266 53.194,23.929 R22.1@53.194,24.923
NetR30_2: R30.2 SB40.1 U8.21 | length 6.9
  L1 w0.127: 36.72,15.346 38.967,15.346 39.231,15.609 40.564,15.609 40.889,15.935 R30.2@40.889,16.126 41.193,16.126 41.663,16.596 U8.21@42.96,16.596
NetSB29_1: SB29.1 SB30.1 SK_BT1.1 | length 21
  L4 w0.3: 30.607,37.889 30.792,37.889 31.045,38.142 31.045,38.376 31.481,38.812 38.088,38.812 39.31,40.034 SK_BT1.1@43.93,40.034
  L4 w0.6: 39.305,43.274 43.07,43.274 SK_BT1.1@45.12,41.224
NRST: CN6.3 CN7.14 D1.K JP5.3 SW4.1 | length 101.6
  L1 w0.15: JP5.3@24.247,22.567 24.174,22.494 22.478,22.494 21.608,21.624 21.608,7.516 23.236,5.888 29.002,5.888 29.362,6.248 35.663,6.248 36.486,5.425 36.486,3.422 37.243,2.665 SW4.1@38.386,2.665
  L1 w0.3: CN7.14@5.79,35.52 7.494,37.224 7.494,47.261 v1@8.405,48.171 ; SW4.1@38.386,2.665 SW4.1@42.486,2.665
  L2 w0.3: v1(9.103,21.033) 20.047,21.033 21.581,22.567 JP5.3@24.247,22.567
  L3 w0.3: CN7.14@5.79,35.52 4.555,34.285 4.555,22.316 5.352,21.519 8.268,21.519 8.754,21.033 v1(9.103,21.033)
  L4 w0.3: CN7.14@5.79,35.52 CN6.3@10.87,35.52 ; v1(8.44,48.203) 8.639,48.203 8.659,48.223 9.633,48.223 9.653,48.203 11.773,48.203 11.809,48.239 12.783,48.239 12.819,48.203 12.861,48.203 13.715,47.349 13.715,47.34 14.057,46.998 D1.K@14.595,46.998
OSC_IN: CN7.29 SB43.2 | length 43.3
  L1 w0.2: v1(13.33,35.292) 13.33,41.476 13.902,42.048 13.902,47.733 14.428,48.259 v1(15.291,48.259)
  L4 w0.2: CN7.29@3.377,15.2 4.573,16.396 12.134,16.396 12.718,16.98 12.718,34.68 v1(13.33,35.292) ; v1(15.291,48.259) 15.3,48.268 SB43.2@15.706,48.268
OSC_OUT: CN7.31 SB44.2 | length 48.3
  L1 w0.2: v1(13.255,34.293) 13.255,34.531 12.7,35.086 12.7,41.987 13.494,42.781 13.494,49.526 14.113,50.145 v1(15.316,50.145)
  L4 w0.2: CN7.31@3.25,12.66 4.516,13.926 11.731,13.926 13.255,15.45 v1(13.255,34.293) ; v1(15.316,50.145) 15.342,50.119 SB44.2@15.706,50.119
PA0: CN7.34 CN8.4 U1.15 | length 67.5
  L1 w0.2: U1.15@28.722,46.652 32.509,46.652 33.08,46.081 33.08,37.449 32.638,37.007 32.638,35.595 32.934,35.299 32.934,34.037 34.995,31.976 34.995,26.49 34.081,25.576 34.081,22.136 34.63,21.587 v1(34.597,21.587)
  L2 w0.2: v1(14.933,19.277) 20.535,19.277 22.385,21.127 27.243,21.127 27.348,21.022 28.397,21.022 28.962,21.587 v1(34.597,21.587)
  L3 w0.2: CN8.4@10.87,10.12 13.963,13.213 13.963,18.296 v1@14.939,19.271
  L4 w0.3: CN7.34@5.79,10.12 CN8.4@10.87,10.12
PA1: CN8.3 SB14.2 U1.16 | length 62.4
  L1 w0.2: U1.16@28.722,47.052 32.647,47.052 33.38,46.319 33.38,34.156 35.361,32.175 35.361,26.285 34.409,25.333 34.409,22.672 34.696,22.385 v1(34.696,22.368)
  L2 w0.2: v1(14.933,20.091) 20.568,20.091 21.944,21.467 28.094,21.467 28.995,22.368 v1(34.696,22.368)
  L3 w0.2: CN8.3@10.87,12.66 13.238,15.028 13.238,18.372 v1@14.945,20.079
  L4 w0.2: CN8.3@10.87,12.66 12.328,12.66 12.708,13.04 SB14.2@13.06,13.04
PA2: CN9.2 SB15.2 U1.17 | length 70.9
  L1 w0.2: U1.17@28.722,47.452 32.836,47.452 33.76,46.528 33.76,34.291 35.727,32.324 35.727,26.227 34.759,25.259 v1(34.759,23.781)
  L2 w0.2: v1(34.759,23.781) 35.198,23.342 35.198,23.315 55.426,23.315 v1(55.688,23.053)
  L3 w0.2: v1(55.688,23.053) 55.688,22.305 57.201,20.792 57.201,9.509 CN9.2@59.13,7.58
  L4 w0.2: 56.637,8.832 57.194,8.832 57.507,8.519 57.507,7.922 57.849,7.58 CN9.2@59.13,7.58
PA3: CN9.1 CN10.37 pad.83 U1.18 | length 79.3
  L1 w0.2: U1.18@28.044,48.155 28.044,48.617 pad.83@28.262,48.835 ; v1(35.083,39.98) 35.083,36.24 35.462,35.861 35.462,34.398 36.974,32.886 36.974,29.588 37.346,29.216 v1(37.638,29.216)
  L2 w0.2: v1(37.638,29.216) 47.665,29.216 49.99,26.891 56.814,26.891 v1(57.061,26.644)
  L3 w0.2: pad.83@28.262,48.835 28.262,48.159 28.607,47.814 35.067,47.814 35.514,47.367 35.514,40.406 v1@35.086,39.977 ; v1(57.061,26.644) 57.059,26.642 57.059,26.104 58.65,24.513 60.199,24.513 61.299,23.413 61.299,7.209 CN9.1@59.13,5.04
  L4 w0.2: CN9.1@59.13,5.04 CN10.37@64.21,5.04
PA4: pad.82 SB5.2 SB41.1 U1.19 | length 40.2
  L1 w0.15: U1.19@27.644,48.404 27.644,48.892 pad.82@27.689,48.937
  L2 w0.2: v1(35.164,40.551) 35.635,40.551 35.968,40.218 35.968,39.577 36.666,38.879 v1(55.405,38.879)
  L3 w0.2: pad.82@27.689,48.937 27.689,47.847 28.063,47.473 34.833,47.473 35.164,47.142 v1(35.164,40.551)
  L4 w0.1: SB5.2@54.55,37.742 54.688,37.604 ; 55.794,37.604 SB41.1@55.94,37.604
  L4 w0.2: 54.688,37.604 55.794,37.604 55.405,37.993 v1(55.405,38.879)
PA5: CN5.6 CN10.11 pad.81 pad.129 U1.20 | length 44.9
  L2 w0.2: pad.129@34.813,42.12 41.042,42.12 42.791,40.371 57.226,40.371 58.013,39.584 CN5.6@59.13,39.584
  L3 w0.2: pad.81@27.239,48.728 27.239,47.55 27.629,47.16 34.524,47.16 34.813,46.871 pad.129@34.813,42.126
  L4 w0.2: CN5.6@59.13,39.584 60.783,39.584 62.307,38.06 CN10.11@64.21,38.06
PA6: CN5.5 CN10.13 pad.80 U1.21 | length 50.9
  L1 w0.15: pad.80@26.816,48.99 26.844,48.962 U1.21@26.844,48.155
  L2 w0.2: v1(32.663,39.784) 33.228,39.784 34.623,38.389 57.185,38.389 58.53,37.044 CN5.5@59.13,37.044
  L3 w0.2: pad.80@26.816,48.99 26.816,47.281 27.288,46.809 33.336,46.809 34.305,45.84 34.305,41.71 33.514,40.919 33.077,40.919 32.663,40.505 v1(32.663,39.784)
  L4 w0.2: CN5.5@59.13,37.044 60.791,37.044 62.315,35.52 CN10.13@64.21,35.52
PA7: CN5.4 pad.79 SB1.2 U1.22 | length 46.8
  L2 w0.2: v1(32.263,39.736) 32.26,39.733 32.26,38.753 33.373,37.64 37.246,37.64 40.098,34.788 43.043,34.788 v1(43.697,34.134) v1@43.697,34.115
  L3 w0.2: pad.79@26.441,48.739 26.441,46.863 26.845,46.459 33.092,46.459 33.81,45.741 33.81,42.065 33.328,41.583 32.775,41.583 32.26,41.068 32.26,39.739 v1(32.263,39.736)
  L4 w0.2: v1(43.697,34.134) 43.699,34.136 49.124,34.136 50.247,35.259 56.158,35.259 ; 56.667,35.417 56.814,35.27 57.291,35.27 58.057,34.504 CN5.4@59.13,34.504
PA8: CN9.7 CN10.25 pad.77 U1.23 | length 62.9
  L1 w0.15: U1.23@26.05,48.161 pad.77@26.05,48.985
  L1 w0.2: v1(34.288,46.692) 35.445,46.692 35.829,46.308 35.829,34.69 37.363,33.156 37.363,30.413 38.853,28.923 v1(38.853,26.644)
  L2 w0.2: pad.77@26.05,48.985 26.05,47.292 26.457,46.885 34.095,46.885 v1(34.288,46.692) ; v1(38.853,26.644) 39.762,26.644 41.444,24.962 56.392,24.962 v1@56.563,24.791
  L3 w0.2: v1(56.563,24.792) 56.562,24.791 56.562,22.848 CN9.7@59.13,20.28
  L4 w0.2: CN9.7@59.13,20.28 CN10.25@64.337,20.28
PA9: CN5.2 pad.76 SB8.2 SB10.1 U1.24 | length 63.2
  L4 w0.2: 24.906,35.859 24.906,36.383 24.024,37.265 24.024,39.868 23.554,40.338 23.554,44.332 24.642,45.42 24.642,46.782 25.643,47.783 pad.76@25.643,48.739 ; 25.224,35.761 25.917,35.761 26.227,35.451 26.227,33.409 26.812,32.824 26.812,32.367 26.335,31.89 23.706,31.89 22.564,30.748 22.564,28.356 23.015,27.905 29.04,27.905 29.229,28.094 48.995,28.094 49.856,28.955 54.566,28.955 54.995,29.384 55.87,29.384 ; SB8.2@56.09,29.412 59.118,29.412 CN5.2@59.13,29.424
PA10: CN9.4 pad.91 SB3.2 SB11.2 U1.51 | length 88.2
  L1 w0.2: pad.91@20.937,40.547 20.941,40.551 U1.51@20.941,41.052 ; CN9.4@58.982,12.512 CN9.4@59.13,12.66 60.507,14.037 v1@60.507,30.724 ; v1(60.484,30.726) v1@60.505,30.726
  L3 w0.2: pad.91@20.937,40.547 28.219,40.547 v1(29.324,39.442)
  L4 w0.2: v1(29.324,39.442) 29.324,38.928 28.985,38.589 28.985,37.704 28.579,37.298 27.155,37.298 26.625,36.768 26.625,33.923 27.214,33.334 27.214,32.154 26.65,31.59 23.918,31.59 22.997,30.669 22.997,28.718 23.336,28.379 27.642,28.379 28.091,28.828 29.702,28.828 29.941,28.589 29.941,28.568 30.032,28.477 45.39,28.477 46.291,29.378 46.291,31.01 47.135,31.854 56.2,31.854 56.2,31.874 ; SB3.2@56.4,31.808 56.4,31.204 56.88,30.724 60.482,30.724 v1(60.484,30.726) ; SB11.2@56.571,13.177 57.232,13.177 57.749,12.66 CN9.4@59.13,12.66
PA13: CN7.13 JP5.5 U1.54 | length 59.1
  L1 w0.1: U1.54@22.444,40.349 22.444,39.439 v1(22.451,39.432)
  L1 w0.2: CN7.13@3.25,35.52 4.565,34.205 6.582,34.205 7.52,33.267 v1(7.52,24.485)
  L2 w0.2: v1(6.993,39.799) 7.288,39.504 9.794,39.504 9.798,39.5 12.777,39.5 12.912,39.635 22.248,39.635 v1(22.451,39.432) ; v1(7.52,24.485) 7.52,21.141 8.448,20.213 11.696,20.213 13.342,18.567 21.237,18.567 22.697,20.027 JP5.5@24.247,20.027
  L4 w0.2: CN7.13@3.25,35.52 4.428,36.698 4.428,38.81 4.996,39.378 6.267,39.378 6.688,39.799 v1(6.993,39.799)
PA14: CN7.15 JP5.7 U1.56 | length 62
  L1 w0.1: CN7.15@3.25,32.98 CN7.15@3.257,32.98 ; v1(23.244,39.444) U1.56@23.244,40.349
  L1 w0.2: CN7.15@3.25,32.98 4.69,31.54 4.69,19.07 v1(4.699,19.061)
  L2 w0.2: v1(4.699,19.061) 7.315,19.061 7.817,19.563 11.622,19.563 13.698,17.487 JP5.7@24.247,17.487 ; v1(6.955,39.208) 6.977,39.186 12.73,39.186 13.036,38.88 16.805,38.88 17.255,38.43 22.788,38.43 23.244,38.886 v1(23.244,39.444)
  L4 w0.2: CN7.15@3.25,32.98 4.628,34.358 4.628,36.264 5.159,36.795 6.527,36.795 6.955,37.223 v1(6.955,39.208)
PA15: CN9.6 CN10.27 U1.57 | length 65.7
  L1 w0.2: v1(21.954,27.669) 21.954,31.16 21.01,32.104 21.01,36.148 21.771,36.909 22.063,36.909 23.644,38.49 U1.57@23.644,40.349
  L2 w0.2: v1(21.954,27.669) 22.537,27.086 39.843,27.086 41.605,25.324 55.874,25.324 55.882,25.316 56.172,25.316 56.18,25.324 v1(56.528,25.323)
  L3 w0.2: v1(56.528,25.323) 57.167,24.684 57.167,22.911 58.573,21.505 59.956,21.505 60.539,20.922 60.539,19.149 CN9.6@59.13,17.74
  L4 w0.2: CN9.6@59.13,17.74 CN10.27@64.337,17.74
PB0: CN10.22 pad.128 R3.1 SB22.1 U1.38 | length 138
  L1 w0.15: v1(17.861,40.497) 17.861,40.279 17.526,39.944 17.526,33.843 19.188,32.181 19.188,28.152 19.678,27.662 v1(19.678,26.319) ; pad.128@18.464,26.334 18.464,25.202 18.192,24.93 18.192,21.829 18.641,21.38 18.641,6.257 19.921,4.977 29.54,4.977 29.796,5.233 32.675,5.233 v1(32.669,5.239) ; v1(20.257,46.319) 20.324,46.252 U1.38@20.941,46.252
  L2 w0.15: v1@19.678,26.313 38.998,26.313
  L2 w0.2: pad.128@18.464,26.334 18.464,26.294 39.536,26.294 41.254,24.576 56.284,24.576 56.418,24.442 56.708,24.442 57.132,24.866 62.446,24.866 63.052,24.26 65.777,24.26 CN10.22@66.877,25.36
  L3 w0.15: v1(17.861,40.497) 17.861,41.059 17.648,41.272 17.648,45.182 18.281,45.815 19.428,45.815 19.43,45.814 19.752,45.814 v1(20.257,46.319)
  L4 w0.15: 14.618,49.321 14.618,47.873 14.965,47.526 16.337,47.526 16.651,47.212 16.651,45.798 16.961,45.489 19.374,45.489 20.204,46.319 v1(20.257,46.319) ; v1(32.669,5.239) 33.199,5.239 R3.1@33.205,5.233
PB1: CN10.24 R4.1 SB23.1 U1.39 | length 123.2
  L1 w0.15: v1(17.461,40.51) 17.202,40.251 17.202,33.617 18.807,32.012 18.807,26.753 19.058,26.502 19.058,24.772 18.672,24.386 v1(18.672,23.859) 19.339,23.859 19.811,23.387 19.811,7.69 22.197,5.304 29.367,5.304 29.786,5.723 33.999,5.723 34.489,5.233 v1(34.782,5.233)
  L1 w0.2: v1(19.526,46.408) 19.526,46.158 19.832,45.852 U1.39@20.941,45.852
  L2 w0.15: v1(13.539,52.457) 13.539,51.806 14.286,51.059 14.286,48.492 14.977,47.801 17.759,47.801 18.151,47.408 18.151,47.055 18.349,46.857 19.077,46.857 v1(19.526,46.408)
  L2 w0.2: v1(18.672,23.859) 18.793,23.98 27.873,23.98 28.109,24.216 41.083,24.216 41.293,24.006 41.293,23.996 41.448,23.841 46.008,23.841 46.033,23.816 58.13,23.816 58.274,23.96 65.737,23.96 CN10.24@66.877,22.82
  L3 w0.15: v1(17.461,40.51) 17.36,40.611 17.36,45.427 17.998,46.065 19.183,46.065 v1(19.526,46.408)
  L4 w0.15: 13.007,54.94 13.007,54.847 13.549,54.305 v1@13.549,52.457 ; v1(34.782,5.233) R4.1@35.275,5.233
PB2: CN7.2 pad.73 U1.27 | length 28.5
  L1 w0.15: pad.73@24.428,48.985 24.428,48.171 U1.27@24.444,48.155
  L4 w0.15: CN7.2@5.79,50.76 7.26,52.229 7.26,55.297 8.122,56.16 13.148,56.16 14.08,55.228 14.08,52.685 14.645,52.12 19.787,52.12 21.108,50.799 21.108,49.924 21.343,49.689 23.724,49.689 pad.73@24.428,48.985
PB3: JP5.9 SB13.1 U1.63 | length 40.6
  L1 w0.2: U1.63@26.044,40.349 26.044,39.42 25.278,38.654 25.278,37.342 26.187,36.433 v1(27.939,36.434) ; v1(30.989,35.124) 30.989,35.104 31.385,34.708 31.385,31.93 32.5,30.815 v1(32.5,25.508)
  L2 w0.2: JP5.9@24.247,14.947 25.647,16.347 32.816,16.347 33.464,16.995 33.464,18.283 33.798,18.617 v1(33.79,18.625)
  L4 w0.2: v1(27.939,36.434) 27.939,36.421 27.97,36.39 27.97,36.043 ; 27.97,35.398 27.97,36.043 ; v1(30.989,35.124) 30.07,36.043 27.97,36.043 ; v1(32.5,25.508) 32.989,25.508 33.79,24.707 v1(33.79,18.625)
PB4: CN10.4 U1.64 | length 50.3
  L1 w0.2: U1.64@26.444,40.349 26.444,39.509 v1(26.453,39.5)
  L2 w0.2: v1(47.628,50.968) 61.679,50.968 61.684,50.973 63.184,49.473 65.497,49.473 CN10.4@66.75,48.22
  L4 w0.2: v1(26.453,39.5) 26.453,45.039 30.05,48.636 34.637,48.636 35.719,49.718 43.338,49.718 44.593,50.973 44.598,50.968 v1(47.628,50.968)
